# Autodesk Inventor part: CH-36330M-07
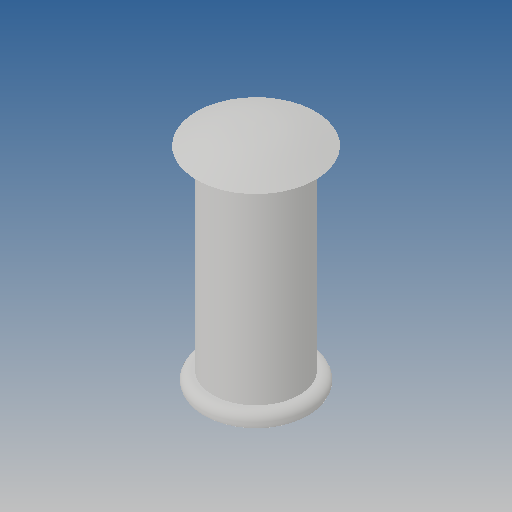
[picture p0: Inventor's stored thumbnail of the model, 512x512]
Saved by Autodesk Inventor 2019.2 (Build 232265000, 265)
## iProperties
Created: 2012-09
Part Number: CH-36330M-07
Material: Ogólny
Document SubType Name: Modeling
Designer: CADENGINEERING4
Density: 1 g/cm^3
Appearance: Domyślna
Author: CADENGINEERING4
Revision Number: ÈÎºÎ
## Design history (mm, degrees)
feature "Ô²½Ç2"
node "Bryła1"
